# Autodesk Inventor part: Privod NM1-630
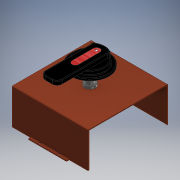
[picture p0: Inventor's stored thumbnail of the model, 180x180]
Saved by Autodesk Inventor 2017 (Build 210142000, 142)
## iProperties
Part Number: Privod NM1-630
Material: Типовые
Document SubType Name: Modeling
Designer: RSagdiev
Density: 1 g/cm^3
Appearance: По умолчанию
Author: RSagdiev
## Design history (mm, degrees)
sketch "Эскиз1"
  geometry: L1 (-45.5, 101.75)-(45.5, 101.75); L2 (45.5, 101.75)-(45.5, 93.25); L3 (45.5, 93.25)-(24.75, 93.25); L4 (-45.5, 93.25)-(-45.5, 101.75); L5 (0, 0)-(119.698, 0); L6 (0, 0)-(-104.809, 0); L7 (0, 94.88)-(0, -60.954); L8 (-24.75, 93.25)-(-20.75, 93.25); L9 (-20.75, 93.25)-(-20.75, 98.25); L10 (-22.75, 100.25)-(-22.75, 100.25); L11 (-24.75, 98.25)-(-24.75, 93.25); L12 (20.75, 93.25)-(20.75, 98.25); L13 (22.75, 100.25)-(22.75, 100.25); L14 (24.75, 93.25)-(20.75, 93.25); L15 (24.75, 98.25)-(24.75, 93.25); L16 (-24.75, 93.25)-(-45.5, 93.25); L17 (-20.75, 93.25)-(-24.75, 93.25); L18 (20.75, 93.25)-(-20.75, 93.25); L19 (24.75, 93.25)-(20.75, 93.25); A1 r 2 centre (-22.75, 98.25) between (-22.75, 100.25) and (-24.75, 98.25); A2 r 2 centre (-22.75, 98.25) between (-20.75, 98.25) and (-22.75, 100.25); A3 r 2 centre (22.75, 98.25) between (22.75, 100.25) and (20.75, 98.25); A4 r 2 centre (22.75, 98.25) between (24.75, 98.25) and (22.75, 100.25); 5 further points
  constraints: 38 end point, 10 point on line, 10 symmetric about line, 8 parallel, 8 point on circle, 4 centre point, 4 horizontal, 4 tangent, 2 perpendicular, 1 concentric, 1 midpoint, 1 vertical, 2 other
  dimensions: "d0" = 93.25 distance between parallel lines of L3 L6 (= 0.5 x Высота); "d1" = 8.5 distance of L1.end L2.end; "d2" = 91 distance between parallel lines of L2 L4 (= 0.5 x Ширина); "d3" = 4 distance of point (-24.75, 100.25) point (-20.75, 100.25); "d4" = 7 distance of point (-20.75, 100.25) L8.end; "d5" = 2 radius of A1 (derived); "d6" = 22.75 distance from line of L4 A1.centre (= 0.25 x d2)
extrude "Выдавливание1" new body sketch "Эскиз1" distance "d7" = 2; taper "d8" = 0 deg
mirror "Зеркальное отражение1"
sketch "Эскиз2"
  geometry: L1 (-45.5, 101.75)-(-45.5, 93.25) reference; L2 (45.5, 93.25)-(45.5, 101.75) reference; L3 (-45.5, -101.75)-(-45.5, -93.25) reference; L4 (45.5, -93.25)-(45.5, -101.75) reference; L5 (-91, 95.25)-(91, 95.25); L6 (91, 95.25)-(91, 93.25); L7 (91, 93.25)-(-91, 93.25); L8 (-91, 93.25)-(-91, 95.25); L9 (-45.5, 93.25)-(-24.75, 93.25) reference
  constraints: 8 end point, 2 parallel, 1 collinear, 1 horizontal, 1 perpendicular
  dimensions: "d13" = 182 distance of L5.start L5.end (= Ширина); "d14" = 2 distance of L5.end L6.end; "d15" = 45.5 distance between parallel lines of L1 L8 (= 0.25 x d13)
extrude "Выдавливание2" join sketch "Эскиз2" distance "d11" = 85 (computed from H1); taper "d12" = 0 deg
mirror "Зеркальное отражение2"
sketch "Эскиз3"
  geometry: L1 (-91, 95.25)-(-45.5, 95.25) reference; L2 (91, -95.25)-(-91, -95.25) reference; L3 (-91, 95.25)-(91, 95.25); L4 (91, 95.25)-(91, -95.25); L5 (91, -95.25)-(-91, -95.25); L6 (-91, -95.25)-(-91, 95.25); 1 further point
  constraints: 8 end point, 2 parallel, 1 horizontal, 1 perpendicular
extrude "Выдавливание3" join sketch "Эскиз3" distance "d16" = 2; taper "d17" = 0 deg
fillet "Сопряжение1" dims "d18" = 2
sketch "Эскиз4"
  geometry: L1 (91, -91.25)-(-91, -91.25) reference; L2 (91, -91.25)-(91, 91.25) reference; L3 (-91, 91.25)-(91, 91.25) reference; L4 (-91, 91.25)-(-91, -91.25) reference; L5 (-91, 91.25)-(-91, -91.25) reference; L6 (-91, -91.25)-(91, 91.25); L7 (91, -91.25)-(91, 91.25) reference; L8 (-91, 91.25)-(91, -91.25); C1 r 5 at (0, 0); 1 further point
  constraints: 4 end point, 1 centre point, 1 coincident
  dimensions: "d19" = 10 diameter of C1
extrude "Выдавливание4" cut sketch "Эскиз4" distance "d20" = 10; taper "d21" = 0 deg
sketch "Эскиз5"
  geometry: C1 r 5 at (0, 0) reference; C2 r 5 at (0, 0); C3 r 8 at (0, 0); 1 further point
  constraints: 2 centre point, 2 coincident
  dimensions: "d22" = 16 diameter of C3
extrude "Выдавливание5" new body sketch "Эскиз5" distance "d23" = 29.66667 (= 0.333333 x H1); taper "d24" = 0 deg
sketch "Эскиз6"
  geometry: C1 r 5 at (0, 0) reference; C2 r 5 at (0, 0); 1 further point
  constraints: 1 centre point, 1 coincident
extrude "Выдавливание6" new body sketch "Эскиз6" distance "d25" = 79.66667 (computed from H1); taper "d26" = 0 deg
sketch "Эскиз7"
  geometry: C1 r 5 at (0, 0) reference; C2 r 13 at (0, 0); C3 r 8 at (0, 0); C4 r 5 at (0, 0); 1 further point
  constraints: 3 centre point, 3 coincident
  dimensions: "d27" = 26 diameter of C2; "d28" = 16 diameter of C3; "d29" = 10 diameter of C4
extrude "Выдавливание7" new body sketch "Эскиз7" distance "d30" = 5; taper "d31" = 0 deg
extrude "Выдавливание8" join sketch "Эскиз7" distance "d32" = 20; taper "d33" = 0 deg
sketch "Эскиз8"
  geometry: C1 r 7 at (0, 0); 1 further point
  constraints: 1 centre point, 1 coincident
  dimensions: "d34" = 14 diameter of C1
extrude "Выдавливание9" new body sketch "Эскиз8" distance "d35" = 3; taper "d36" = 0 deg
fillet "Сопряжение2" dims "d37" = 3
sketch "Эскиз9"
  geometry: L1 (1, 13.17)-(-1, 13.17); L2 (-1, 13.17)-(-1, -13.17); L3 (-1, -13.17)-(1, -13.17); L4 (1, -13.17)-(1, 13.17); L5 (1, 13.17)-(-1, -13.17); L6 (-1, 13.17)-(1, -13.17); L7 (17.109, -1)-(-17.109, -1); L8 (-17.109, -1)-(-17.109, 1); L9 (-17.109, 1)-(17.109, 1); L10 (17.109, 1)-(17.109, -1); L11 (17.109, -1)-(-17.109, 1); L12 (-17.109, -1)-(17.109, 1); C1 r 4 at (0, 0) reference; C2 r 5 at (0, 0) reference; 1 further point
  constraints: 24 end point, 4 midpoint, 4 parallel, 2 horizontal, 2 perpendicular
  dimensions: "d38" = 2 distance of L3.end L2.end; "d39" = 2 distance of L7.end L8.end
extrude "Выдавливание10" cut sketch "Эскиз9" distance "d40" = 1; taper "d41" = 0 deg
sketch "Эскиз10"
  geometry: C1 r 17.5 at (0, 0); A1 r 4 centre (0, 0) between (1, -3.873) and (3.873, -1) reference; 1 further point
  constraints: 1 centre point, 1 coincident
  dimensions: "d42" = 35 diameter of C1
extrude "Выдавливание11" new body sketch "Эскиз10" distance "d43" = 6; taper "d44" = 0 deg; dims "d48" = 3, "d49" = 0
sketch "Эскиз11"
  geometry: C1 r 7 at (0, 0); C2 r 22.5 at (0, 0); 1 further point
  constraints: 2 centre point, 1 coincident
  dimensions: "d45" = 45 diameter of C2
extrude "Выдавливание12" join sketch "Эскиз11" distance "d46" = 6; taper "d47" = 0 deg
sketch "Эскиз12"
  geometry: L1 (-4, -49.361)-(4, -49.361); L2 (10, -43.361)-(10, 10.738); L3 (-10, 10.738)-(-10, -43.361); L4 (-10, -49.361)-(10, 14.361); L5 (10, -49.361)-(-10, 14.361); L6 (-12, 12.738)-(12, 12.738); A1 r 17.5 centre (0, 0) between (10, 14.361) and (0, -17.5) reference; A2 r 17.5 centre (0, 0) between (10, 14.361) and (0, -17.5) reference; A3 r 6 centre (-4, -43.361) between (-10, -43.361) and (-4, -49.361); A4 r 6 centre (4, -43.361) between (4, -49.361) and (10, -43.361); A5 r 2 centre (-12, 10.738) between (-10, 10.738) and (-12, 12.738); A6 r 2 centre (12, 10.738) between (12, 12.738) and (10, 10.738); A7 r 17.5 centre (0, 0) between (12, 12.738) and (-12, 12.738)
  constraints: 16 point on circle, 12 end point, 8 tangent, 6 point on line, 5 centre point, 2 equal radius, 2 horizontal, 2 midpoint, 1 coincident, 1 parallel, 1 perpendicular
  dimensions: "d63" = 20 distance of L4.end L5.end; "d64" = 6 radius of A3; "d66" = 10 distance from line of A1.centre L3; "d67" = 2 radius of A5; "d68" = 2 radius of A6 (derived)
extrude "Выдавливание13" join sketch "Эскиз12" distance "d55" = 10; taper "d56" = 0 deg
fillet "Сопряжение9" dims "d69" = 1
fillet "Сопряжение10" dims "d70" = 1
sketch "Эскиз13"
  geometry: L1 (0, 7.748)-(0, -17.5); L2 (-4, 7.748)-(-4, -17.5); L3 (4, -17.5)-(4, 7.748); A1 r 17.5 centre (0, 0) between (17.5, 0) and (0, -17.5) reference; A2 r 4 centre (0, 7.748) between (4, 7.748) and (-4, 7.748); A3 r 4 centre (0, -17.5) between (-4, -17.5) and (4, -17.5); 2 further points
  constraints: 8 end point, 5 point on circle, 4 tangent, 2 centre point, 1 midpoint, 1 parallel, 1 vertical
  dimensions: "d71" = 8 diameter of A3
extrude "Выдавливание14" cut sketch "Эскиз13" distance "d72" = 0.1; taper "d73" = 0 deg
sketch "Эскиз14"
  geometry: L1 (0, 9.652)-(1.649, 6.796); L2 (1.649, 6.796)-(-1.649, 6.796); L3 (-1.649, 6.796)-(0, 9.652); A1 r 4 centre (0, 7.748) between (4, 7.748) and (-4, 7.748) reference; 2 further points
  constraints: 6 end point, 1 coincident, 7 other
extrude "Выдавливание15" join sketch "Эскиз14" distance "d74" = 0.1; taper "d75" = 0 deg
node "Непосредственное редактирование1"
node "Твердое тело1"
node "Спроецированная петля1"
node "Твердое тело2"
node "Твердое тело3"
node "Твердое тело4"
node "Твердое тело5"
node "Спроецированная петля2"
node "Твердое тело6"
node "Спроецированная петля3"
feature "Масштаб1"
other parameters: "H1" = 89 [user parameter; used in 3 equation terms], "Высота" = 186.5 [user parameter; used in 1 equation term], "Ширина" = 182 [user parameter; used in 2 equation terms]
